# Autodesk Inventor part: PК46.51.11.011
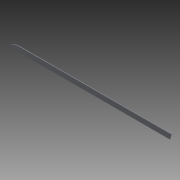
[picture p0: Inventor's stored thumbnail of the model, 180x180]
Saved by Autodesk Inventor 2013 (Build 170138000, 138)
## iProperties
Shininess: 64.0
Length Units: 11269
Angle Units: 11279
Time Units: 11290
Mass Units: 11283
Length Display Precision: 3
Angle Display Precision: 2
Compacted: True
Part Number: PК46.51.11.011
Document SubType Name: Листовой материал
Created: 2004-12
Material: Steel, Mild
Designer: =<Author>
Manufacturer: Standard
Standards Organization: Custom
Description: strip seal
Density: 7.86 g/cm^3
Sheet Metal Rule: По умолчанию
Mass: 110.279 g
Surface Area: 159.82 cm^2
Volume: 14.0304 cm^3
Density: 0.0
Volumn: 0.0
Area: 0.0
PropertySet Name: Model Information
Control State: 0
Master: False
Checked Out: False
Checked Out Date: 2008-10-15
Last Check In Date: 2008-10-15
Author: PVitaliy
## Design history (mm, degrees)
node "ФлнОтгиб1"
feature "Вырез1" dims "d10" = 2 (= Толщина), "d11" = 0
body "Solid1"
sketch "Эскиз1"
  geometry: L1 (0, 0)-(485, 0)
  constraints: 2 end point, 1 horizontal, 1 other
  dimensions: "d0" = 485 distance of L1.start L1.end
feature "Пластина1" dims "d2" = 15, "d3" = 2 (= Ширина_просечки), "d5" = 4 (= Минимальный_остаток), "d7" = 2 (= Радиус_гибки), "d8" = 2, "Толщина" = 2
feature "Изгиб1" dims "d3" = 2 (= Ширина_просечки), "d4" = 1 (= Глубина_просечки), "d5" = 4 (= Минимальный_остаток), "d6" = 2 (= Радиус_гибки), "d7" = 2 (= Радиус_гибки), "d8" = 2, "Толщина" = 2, "Зазор_стыка" = 0.01
sketch "Эскиз2"
  geometry: L1 (485, 15)-(0, 15) reference; L2 (0, 0)-(0, 15) reference; L3 (485, 0)-(0, 0) reference; L4 (485, 0)-(485, 15) reference; L5 (485, 15)-(480.981, 0); A1 r 45 centre (38.541, -30) between (38.541, 15) and (5, 0)
  constraints: 3 point on line, 2 end point, 2 point on circle, 1 centre point, 1 tangent
  dimensions: "d12" = 15 deg angle of L5 L4; "d13" = 45 radius of A1; "d14" = 480 distance from line of A1.end L4
other parameters: "Радиус_гибки" = 2 (= Толщина), "Ширина_просечки" = 2 (= Толщина), "Глубина_просечки" = 1 (= 0.5 x Толщина), "Размер_высечки" = 8 (= 4 x Толщина), "Минимальный_остаток" = 4 (= 2 x Толщина), "Радиус_перехода" = 2 (= Радиус_гибки), "JacobiRadiusSize" = 2 (= Толщина), "GapSize" = 2 (= Толщина)
